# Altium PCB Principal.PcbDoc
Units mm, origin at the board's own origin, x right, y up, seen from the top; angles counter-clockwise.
Board outline 152.4 x 101.6 mm, 2 copper layers (Top Layer, Bottom Layer); 38 components, 56 nets, 194 pads, 50 vias.
Unrouted connection lines stored in the file: 1.
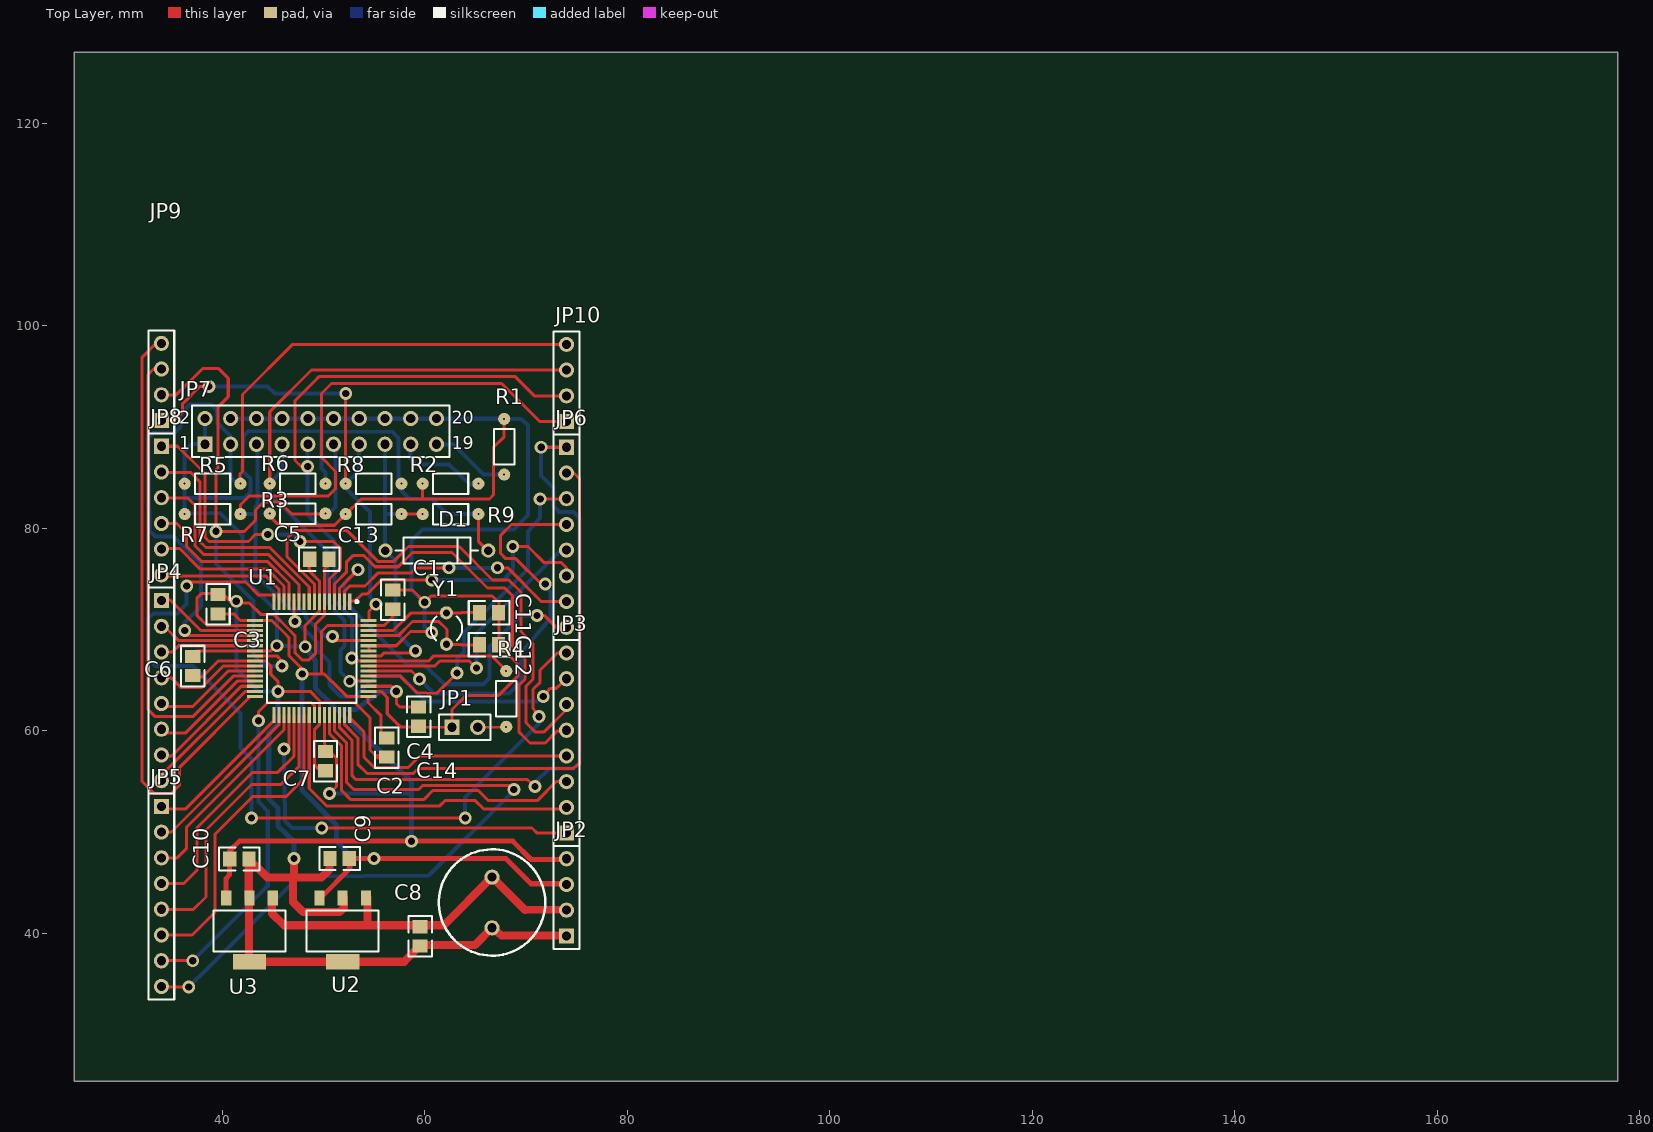
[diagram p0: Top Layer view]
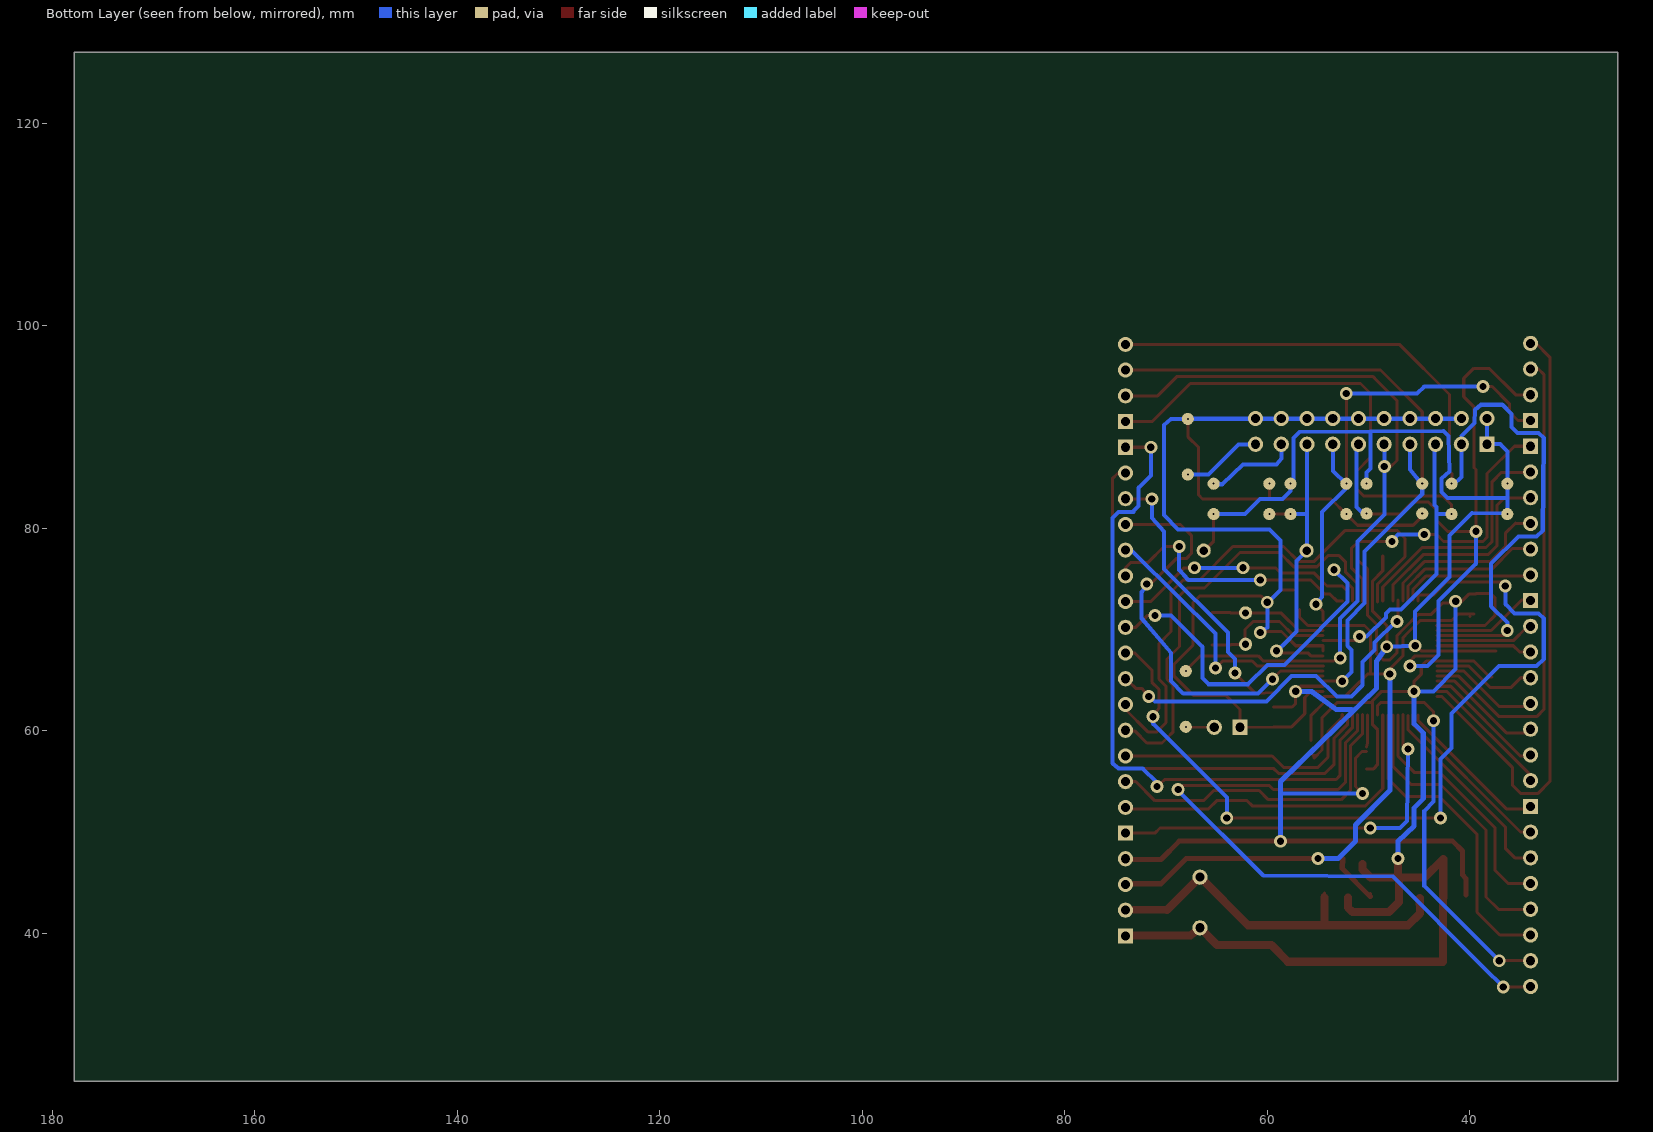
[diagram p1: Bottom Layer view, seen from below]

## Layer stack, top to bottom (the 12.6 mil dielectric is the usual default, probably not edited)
Top Layer: signal copper 0.0356
Dielectric: dielectric 0.32, FR-4, Dk 4.8
Bottom Layer: signal copper 0.0356

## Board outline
25.4,25.4 177.8,25.4 177.8,127 25.4,127

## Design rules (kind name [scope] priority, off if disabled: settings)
Clearance [All] p1: gap=0.2
ComponentClearance [All] p1: gap=0.254 collisioncheckmode=0
PolygonConnect [All] p1: connectstyle=Relief reliefconductorwidth=0.254 reliefentries=4 polygonreliefangle="90 Angle"
RoomDefinition Principal1 [InComponentClass('Principal1')] p1: confinementstyle=ConfineIn formatcopy=TRUE outline 0,0 50.8,0 50.8,25.4 0,25.4
RoutingLayers [All] p1: top layer=Horizontal bottom layer=Vertical
RoutingVias [All] p1: holewidth=0.711 width=1.27 viastyle="Through Hole" minholewidth=0.711 minwidth=1.27 maxholewidth=0.711 maxwidth=1.27
SolderMaskExpansion [All] p1: expansion=0.102
TestPointUsage [All] p1: valid=0 allowmultiple=FALSE
Testpoint [All] p1: side=15 testpointundercomponent=TRUE minsize=1.016 maxsize=2.54 preferedsize=1.524 minholesize=0 maxholesize=1.016 preferedholesize=0.813 testpointgrid=0.025 style=1023 order=1234567890
Width [All] p1: maxlimit=0.8 minlimit=0.2 preferedwidth=0.2 toplayer_prefwidth=0.3 bottomlayer_prefwidth=0.4 minimp=50.000000 maximp=50.000000 favimp=50.000000
16 further rules are at their usual default settings.

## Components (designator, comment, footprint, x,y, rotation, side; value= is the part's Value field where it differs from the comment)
C1 "Cap" R2012-0805 56.85,72.95 r270 top
C2 "Cap" R2012-0805 56.25,58.35 r90 top
C3 "Cap" R2012-0805 39.6,72.5 r270 top
C4 "Cap" R2012-0805 59.4,61.4 r90 top
C5 "Cap" R2012-0805 49.6,76.95 r180 top
C6 "Cap" R2012-0805 37.1,66.4 r90 top
C7 "Cap" R2012-0805 50.2,57 r90 top
C8 "Cap" R2012-0805 59.55,39.7 r90 top
C9 "Cap" R2012-0805 51.6,47.4 r0 top
C10 "Cap" R2012-0805 41.7,47.35 r180 top
C11 "Cap" R2012-0805 66.35,71.65 r0 top
C12 "Cap" R2012-0805 66.35,68.5 r0 top
C13 "Cap" "Res 5mm" 57.7,81.4 r180 top
C14 "Cap Pol1" RB5-10.5 66.65,43.05 r270 top
D1 "Diode" DIODE-0.4 61.2,77.8 r0 top
JP1 "JTAG" HDR1X2 62.7,60.35 r0 top
JP2 "Header 4" HDR1X4 74,39.75 r90 top
JP3 "Header 8" HDR1X8 74,49.9 r90 top
JP4 "Header 8" HDR1X8 34,72.86 r270 top
JP5 "Header 8" HDR1X8 34,52.54 r270 top
JP6 "Header 8" HDR1X8 74,88 r270 top
JP7 "JTAG P5" HDR2X10 38.3,88.3 r0 top
JP8 "Header 6" HDR1X6 34,88.1 r270 top
JP9 "Header 4" HDR1X4 34,90.64 r90 top
JP10 "Header 4" HDR1X4 74,90.54 r90 top
R1 "Res1" "Res 5mm" 67.85,85.3 r90 top
R2 "Res1" "Res 5mm" 65.3,84.4 r180 top
R3 "Res1" "Res 5mm" 50.2,81.45 r180 top
R4 "Res1" "Res 5mm" 68.05,65.9 r270 top
R5 "Res1" "Res 5mm" 36.3,84.4 r0 top
R6 "Res1" "Res 5mm" 50.2,84.4 r180 top
R7 "Res1" "Res 5mm" 36.3,81.4 r0 top
R8 "Res1" "Res 5mm" 57.7,84.4 r180 top
R9 "Res1" "Res 5mm" 59.8,81.4 r0 top
U1 "LPC2114/LPC2124" F-QFP10X10-G64/P.5N 48.85,67.15 r270 top
U2 "LD1117S18" SOT223 58,37.2 r180 top
U3 "LD1117S33" SOT223 48.8,37.2 r180 top
Y1 "XTAL 16Mhz" BCY-W2/D3.1 62.15,70.1 r180 top

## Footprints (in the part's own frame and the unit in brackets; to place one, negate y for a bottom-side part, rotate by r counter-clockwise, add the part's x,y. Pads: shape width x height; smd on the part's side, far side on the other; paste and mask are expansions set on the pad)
BCY-W2/D3.1 [mm]
  round 1.3 hole 0.7: 1(0,1.55) 2(0,-1.55)
  silkscreen extent -1.55,-1.19 1.55,1.17
DIODE-0.4 [mm]
  round 1.4 hole 0.85: 1(-5.08,0) 2(5.08,0)
  silkscreen extent -4.06,-1.27 4.06,1.27
F-QFP10X10-G64/P.5N [mm]
  rect 1.6x0.3 smd: 1(-5.6,3.75) 2(-5.6,3.25) 3(-5.6,2.75) 4(-5.6,2.25) 5(-5.6,1.75) 6(-5.6,1.25) 7(-5.6,0.75) 8(-5.6,0.25) 9(-5.6,-0.25) 10(-5.6,-0.75) 11(-5.6,-1.25) 12(-5.6,-1.75) 13(-5.6,-2.25) 14(-5.6,-2.75) 15(-5.6,-3.25) 16(-5.6,-3.75) 33(5.6,-3.75) 34(5.6,-3.25) 35(5.6,-2.75) 36(5.6,-2.25) 37(5.6,-1.75) 38(5.6,-1.25) 39(5.6,-0.75) 40(5.6,-0.25) 41(5.6,0.25) 42(5.6,0.75) 43(5.6,1.25) 44(5.6,1.75) 45(5.6,2.25) 46(5.6,2.75) 47(5.6,3.25) 48(5.6,3.75)
  rect 0.3x1.6 smd: 17(-3.75,-5.6) 18(-3.25,-5.6) 19(-2.75,-5.6) 20(-2.25,-5.6) 21(-1.75,-5.6) 22(-1.25,-5.6) 23(-0.75,-5.6) 24(-0.25,-5.6) 25(0.25,-5.6) 26(0.75,-5.6) 27(1.25,-5.6) 28(1.75,-5.6) 29(2.25,-5.6) 30(2.75,-5.6) 31(3.25,-5.6) 32(3.75,-5.6) 49(3.75,5.6) 50(3.25,5.6) 51(2.75,5.6) 52(2.25,5.6) 53(1.75,5.6) 54(1.25,5.6) 55(0.75,5.6) 56(0.25,5.6) 57(-0.25,5.6) 58(-0.75,5.6) 59(-1.25,5.6) 60(-1.75,5.6) 61(-2.25,5.6) 62(-2.75,5.6) 63(-3.25,5.6) 64(-3.75,5.6)
  silkscreen extent -5.72,-4.4 4.4,4.58
HDR1X2 [mm]
  rect 1.5x1.5 hole 0.9: 1(0,0)
  round 1.5 hole 0.9: 2(2.54,0)
  silkscreen extent -1.27,-1.27 3.81,1.27
HDR1X4 [mm]
  rect 1.5x1.5 hole 0.9: 1(0,0)
  round 1.5 hole 0.9: 2(2.54,0) 3(5.08,0) 4(7.62,0)
  silkscreen extent -1.27,-1.27 8.89,1.27
HDR1X6 [mm]
  rect 1.5x1.5 hole 0.9: 1(0,0)
  round 1.5 hole 0.9: 2(2.54,0) 3(5.08,0) 4(7.62,0) 5(10.16,0) 6(12.7,0)
  silkscreen extent -1.27,-1.27 13.97,1.27
HDR1X8 [mm]
  rect 1.5x1.5 hole 0.9: 1(0,0)
  round 1.5 hole 0.9: 2(2.54,0) 3(5.08,0) 4(7.62,0) 5(10.16,0) 6(12.7,0) 7(15.24,0) 8(17.78,0)
  silkscreen extent -1.27,-1.27 19.05,1.27
HDR2X10 [mm]
  rect 1.5x1.5 hole 0.9: 1(0,0)
  round 1.5 hole 0.9: 2(0,2.54) 3(2.54,0) 4(2.54,2.54) 5(5.08,0) 6(5.08,2.54) 7(7.62,0) 8(7.62,2.54) 9(10.16,0) 10(10.16,2.54) 11(12.7,0) 12(12.7,2.54) 13(15.24,0) 14(15.24,2.54) 15(17.78,0) 16(17.78,2.54) 17(20.32,0) 18(20.32,2.54) 19(22.86,0) 20(22.86,2.54)
  silkscreen extent -1.27,-1.27 24.13,3.81
R2012-0805 [mm]
  rect 1.3x1.5 smd: 1(-0.95,0) 2(0.95,0)
  silkscreen extent -2,-1.15 2,1.15
RB5-10.5 [mm]
  round 1.5 hole 0.9: 1(-2.5,0) 2(2.5,0)
  silkscreen extent -5.25,-5.25 5.25,5.25
"Res 5mm" [mm]
  round 1.2 hole 0.2: 1(0,0) 2(5.5,0)
  silkscreen extent 1,-1.02 4.5,1.02
SOT223 [mm]
  rect 1x1.5 smd: 1(3.8,-6.3) 3(8.4,-6.3) 4(6.1,-6.3)
  rect 3.3x1.5 smd: 4(6.096,0)
  silkscreen extent 2.54,-5.08 9.65,-1.02

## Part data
C1 C2 C3 C4 C5 C6 C7 C8 C9 C10 C11 C12 C13: "Capacitor"
C14: "Polarized Capacitor (Radial)"
D1: "Default Diode"
JP1 JP2: library part "Header 2", "Header, 2-Pin"
JP3 JP4 JP5 JP6: "Header, 8-Pin"
JP7: library part "Header 10X2", "Header, 10-Pin, Dual row"
JP8: "Header, 6-Pin"
JP9: library part "Header 8", "Header, 8-Pin"
JP10: "Header, 4-Pin"
R1 R2 R3 R4 R5 R6 R7 R8 R9: "Resistor"
U2 U3: library part LF27ACDT, "Very Low Drop Voltage Regulator with Inhibit"
Y1: library part XTAL, "Crystal Oscillator"

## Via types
v1: diameter 1.27, hole 0.711, Top Layer to Bottom Layer, 50 vias

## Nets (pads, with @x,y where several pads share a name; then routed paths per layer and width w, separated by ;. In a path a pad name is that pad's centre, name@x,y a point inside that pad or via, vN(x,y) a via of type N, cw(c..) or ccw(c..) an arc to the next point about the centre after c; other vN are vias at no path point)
GND: C1.1 C2.1 C3.1 C4.1 C5.1 C6.1 C7.1 C8.1 C9.1 C10.1 C11.2 C12.2 C13.2 C14.2 JP1.1 JP2.1 JP7.4 JP7.6 JP7.8 JP7.10 JP7.12 JP7.14 JP7.16 JP7.18 JP7.20 R1.2 R2.2 R3.2 U1.6 U1.18 U1.25 U1.42 U1.50 U1.58 U1.59 U2.4 U3.4 | length 300.2
  Top Layer w0.3: C6.1@37.8,65.3 38,65.3 39.6,66.9 U1.25 44.3,66.9 44.8,66.4 44.8,65.6 45.5,64.9 v1(45.5,63.9) 48.7,63.9 49.6,63 49.6,60.6 49.1,60.1 49.1,56.7 49.5,56.25 C7.1@50.2,56.25 ; U1.18@43.3,70.4 38.5,70.4 37.5,71.4 37.5,73.1 37.95,73.55 39.4,73.55 39.45,73.5 40.1,73.5 41,72.6 42.7,72.6 43.8,71.5 45.1,71.5 46.5,70.1 47.2,69.4 47.2,67.7 47.9,67 48.578,67.005 49.2,67.6 49.2,70.5 50.1,71.4 50.1,76 C5.1@50.9,76.7 ; R3.2@44.4,81.5 45.6,80.3 49.5,80.3 51.1,80.3 C13.2 53.7,82.9 66.4,82.9 66.8,83.3 66.8,88 67.85,89.05 R1.2 ; 49.6,62.8 53.1,62.8 54.6,61.3 54.6,58.1 55.4,57.3 ; U1.50@54.5,63.9 55.7,63.9 56.3,63.3 56.3,61.7 57.6,60.4 58.9,60.4 59.399,60.393 JP1.1 62.7,62.1 64.1,63.5 67.3,63.5 69.2,65.4 69.2,66.6 67.334,68.464 67.334,71.664 67.334,72.666 66.7,73.3 60.6,73.3 v1(60,72.7) 58.8,73.9 C1.1@57.35,73.9 ; U1.58@54.5,67.9 54.5,68.4 57.2,68.4 58.6,69.8 v1@60.1,69.8 ; 55.3,57.55 55.5,57.55 ; 59.8,82.9 R2.2@59.8,84.35 ; JP7.20@61.144,90.816 JP7.20@61.144,90.83
  Top Layer w0.8: 47,45.5 47,43.1 48,42.1 51.6,42.1 52.05,42.55 U2.4@52.05,43.55 ; 47.1,45.5 v1(47.1,47.4) ; C9.1@50.6,46.847 50.6,46.3 49.8,45.5 44.474,45.5 42.626,47.348 42.626,43.524 42.654,43.496 42.654,37.2 52.054,37.2 58,37.2 58,37.25 59.6,38.85 64.95,38.85 C14.2 ; C14.2@66.55,40.55 67.6,39.8 JP2.1@73.5,39.8
  Bottom Layer w0.4: JP7.4@40.824,90.816 67.834,90.816 R1.2 69.5,90.8 70.2,90.2 70.2,81.3 68.8,79.9 59.8,79.9 58.7,78.8 58.7,73.9 59.9,72.7 v1(60,72.7) 60,70.2 v1(60.7,69.7) ; v1(41.4,72.8) 41.4,66.1 43.6,63.9 v1(45.5,63.9)
  Bottom Layer w0.5: v1(45.5,63.9) 45.5,60.7 44.6,59.8 44.6,53.3 45.5,52.4 45.5,50.6 47.1,49.1 v1(47.1,47.4)
NetC1_2: C1.2 C2.2 C3.2 C9.2 JP2.3 U1.17 U1.49 U1.63 U2.3 | length 86.7
  Top Layer w0.3: C3.2 41.15,71.55 41.8,70.9 44.9,70.9 46.1,69.7 46.6,69.2 46.6,67.4 47.9,66.1 v1(47.9,65.6) 49.4,65.6 50.1,65.6 51.5,64.2 52.3,63.4 54.4,63.4 54.4,62.8 55.7,61.5 C2.2@55.7,59.05 ; 49.8,65.6 49.8,69.8 50.4,70.4 56,70.4 56.8,71.2 C1.2@56.8,72 ; U2.3@49.834,43.628 U2.3@49.834,43.917
  Top Layer w0.5: U2.3@49.834,43.628 52.6,46.4 C9.2 68,47.4 70.5,44.9 JP2.3@73.7,44.9
  Bottom Layer w0.5: v1(47.9,65.6) 47.9,54.1 51.3,50.7 51.3,49.1 53,47.4 v1(55,47.4)
NetC4_2: C4.2 C5.2 C6.2 C7.2 C10.2 D1.2 JP2.4 JP7.1 JP7.2 R5.1 R6.1 R7.1 R8.1 R9.2 U1.7 U1.23 U1.43 U1.51 U3.3 | length 193.7
  Top Layer w0.3: C6.2@37.4,67.9 44.8,67.9 v1(45.4,68.4) ; v1@48.158,68.25 v1(48.2,68.3) 48.2,70.4 49.6,71.8 49.6,74.8 48.6,75.8 C5.2@48.6,77.25 ; U1.43 50.1,58.8 C7.2@50.2,58.4 ; C7.2 50.65,57.95 51.3,57.3 51.3,54.5 v1(50.6,53.8) ; U1.51@54.5,64.4 56.7,64.4 v1(57.2,63.9) 57.2,62.7 57.55,62.35 C4.2 ; R9.2 65.3,78.73 D1.2@66.23,77.8
  Top Layer w0.5: U3.3@40.4,43.8 40.4,45.4 40.726,45.775 40.726,48.126 41.7,49.1 v1(58.7,49.1) 68.7,49.1 70.5,47.3 JP2.4@74.3,47.32
  Bottom Layer w0.4: 36.3,83 42.2,83 42.8,83.6 42.8,84.9 42,85.6 42.1,89.1 42.6,89.6 49.8,89.549 56.8,89.5 57.4,88.9 R8.1@57.4,84.5 ; JP7.1@38.284,88.276 JP7.2@38.284,90.816 ; JP7.1 37,88.3 36.3,87.6 36.3,84.2 36.3,81.45 39.8,81.5 42,79.3 42,75.2 45.4,71.8 v1(45.4,68.4) v1@48.108,68.3 ; 49.8,89.5 49.8,85.9 50.2,85.5 R6.1@50.2,84.35 ; v1(50.6,53.8) 58.7,53.8 ; R8.1 57.7,83.7 58.5,82.9 60.7,82.9 62.2,81.4 R9.2
  Bottom Layer w0.5: v1(48.2,68.3) 49.2,66.9 49.2,64.2 58.7,55 v1(58.7,49.1) ; 51.7,62.1 53.2,62.1 55.659,63.904 v1@57.1,63.9
NetC8_2: C8.2 C14.1 JP2.2 U2.1 U3.1 | length 37.6
  Top Layer w0.3: U2.1@54.334,44.009 54.334,43.79 U2.1@54.553,43.79
  Top Layer w0.8: U3.1@44.95,43.5 44.934,41.966 46.1,40.8 61.9,40.8 C14.1 69.9,42.3 JP2.2@74,42.34 ; 54.3,40.8 54.35,40.85 U2.1@54.35,43.55
NetC11_1: C11.1 U1.62 Y1.2 | length 11.7
  Top Layer w0.3: U1.62@54.5,69.9 56.9,69.9 58.614,71.614 63.576,71.614 63.626,71.664 C11.1@65.434,71.664
NetC12_1: C12.1 U1.61 Y1.1 | length 13.4
  Top Layer w0.3: U1.61@54.5,69.4 57.4,69.4 58.8,70.8 61.4,70.8 62.2,70 62.184,68.514 63.576,68.514 63.626,68.464 C12.1@65.434,68.464
NetC13_1: C13.1 D1.1 JP7.15 R9.1 U1.57 | length 30.2
  Top Layer w0.3: U1.57@54.5,67.4 55.7,67.4 56,67.7 58.7,67.7 v1(59.1,67.9) ; C13.1 R9.1
  Bottom Layer w0.4: 56.064,81.4 C13.1 ; JP7.15@56.064,88.276 56.064,77.806 57.1,76.77 57.1,69.8 58.4,68.5 v1(59.1,67.9)
NetJP1_2: JP1.2 R4.2 | length 2.9
  Top Layer w0.3: JP1.2 R4.2 R4.2@68.1,60.45
NetJP3_1: JP3.1 U1.36 | length 39.1
  Top Layer w0.3: v1(46.1,58.2) 46.6,58.5 U1.36 U1.36@46.6,61.625 ; v1(49.835,50.394) 70.6,50.4 71.1,49.9 JP3.1
  Bottom Layer w0.4: v1(46.1,58.2) 46.2,51.1 46.906,50.394 v1(49.835,50.394)
NetJP3_2: JP3.2 U1.40 | length 33.5
  Top Layer w0.3: U1.40 48.6,60.409 48.6,54.3 50.3,52.6 61.5,52.6 62,53.1 65,53.1 65.8,52.3 JP3.2@73.6,52.3
NetJP3_3: JP3.3 U1.44 | length 32.1
  Top Layer w0.3: U1.44@50.6,61.6 50.6,59.7 51.8,58.5 51.8,54.1 52.7,53.2 59.9,53.2 60.8,54.1 65.3,54.1 66.3,53.1 71.1,53.1 73,55 JP3.3
NetJP3_4: JP3.4 U1.48 | length 25.7
  Top Layer w0.3: U1.48@52.6,61.6 52.6,61.3 54,59.9 54,57.4 55,56.4 58.4,56.4 59.52,57.52 JP3.4
NetJP3_5: JP3.5 U1.4 | length 43.3
  Top Layer w0.3: U1.4@51.1,72.8 51.1,74.5 52.3,75.7 52.3,76.7 52.9,77.3 54,77.3 55.1,76.2 57.4,76.2 58.8,77.6 62.7,77.6 66.2,74.1 67.9,74.1 68.676,73.324 68.676,68.324 69.9,67.1 69.9,65.1 69.3,64.5 69.3,59.9 69.9,59.3 70.4,58.8 71.9,58.8 73.1,60 JP3.5@73.6,60
NetJP3_6: JP3.6 U1.8 | length 54.1
  Top Layer w0.3: U1.8@49.1,72.7 49.1,74.5 46.4,77.2 46.4,79 47.2,79.8 52.3,79.8 55.4,76.7 56.9,76.7 58.4,78.2 63.4,78.2 66.7,74.9 68.3,74.9 69.5,73.7 69.5,69.8 70.7,68.6 70.7,65.1 70,64.4 70,60.8 70.9,59.9 71.8,59.9 74,62.1 JP3.6
NetJP3_7: JP3.7 U1.12 | length 36
  Top Layer w0.3: U1.12@47.1,72.9 47.1,71.1 v1(47.2,70.8) ; v1(71.7,63.4) 72.4,64.2 73,64.2 JP3.7@73.6,64.8
  Bottom Layer w0.4: v1(47.2,70.8) 47.3,70.8 49.4,68.7 49.4,68 50.6,66.8 50.6,64.5 51.7,63.4 53.1,63.4 55.2,65.4 57.6,65.4 60.1,62.9 71.1,62.9 v1(71.7,63.4)
NetJP3_8: JP3.8 U1.16 | length 84.9
  Top Layer w0.3: v1@36.5,74.7 42.3,74.7 43.6,73.4 45.1,73.4 U1.16@45.1,72.8 ; v1(42.9,51.4) v1(64,51.4) v1@64.135,51.714 ; v1(71.3,61.4) 70.7,62.2 70.7,64.1 71.4,64.8 71.4,66 73.08,67.68 JP3.8
  Bottom Layer w0.4: v1(36.5,74.3) 36.5,72.5 35.6,71.6 33.2,71.6 32.7,71.1 32.7,67.1 33.4,66.4 37.1,66.4 41.8,61.7 41.8,58.3 42.9,57.2 v1(42.9,51.4) ; v1(64,51.4) 64,53.4 71.3,60.7 v1(71.3,61.4)
NetJP4_1: JP4.1 U1.19 | length 10.1
  Top Layer w0.3: JP4.1@34.4,72.9 34.9,72.9 37.9,69.9 U1.19
NetJP4_2: JP4.2 U1.21 | length 9.8
  Top Layer w0.3: JP4.2 34.4,70.2 35.7,68.9 U1.21
NetJP4_3: JP4.3 U1.22 | length 9.2
  Top Layer w0.3: JP4.3@34.3,67.8 35.1,67.8 35.7,68.4 U1.22
NetJP4_4: JP4.4 U1.26 | length 10.5
  Top Layer w0.3: JP4.4 34.96,65.24 35.9,64.3 38,64.3 40.1,66.4 U1.26
NetJP4_5: JP4.5 U1.27 | length 10.5
  Top Layer w0.3: JP4.5@34.2,62.4 37.1,62.4 40.6,65.9 U1.27
NetJP4_6: JP4.6 U1.29 | length 11.3
  Top Layer w0.3: JP4.6@34.1,59.8 36.4,59.8 41.5,64.9 U1.29
NetJP4_7: JP4.7 U1.30 | length 11.9
  Top Layer w0.3: JP4.7@34.2,57.5 35,57.5 41.9,64.4 U1.30
NetJP4_8: JP4.8 U1.31 | length 12.7
  Top Layer w0.3: JP4.8@34,55.6 42.3,63.9 U1.31
NetJP5_1: JP5.1 U1.33 | length 15
  Top Layer w0.3: JP5.1@34.3,52.3 36.4,52.3 45.1,61 U1.33
NetJP5_2: JP5.2 U1.34 | length 17
  Top Layer w0.3: JP5.2 35,50 45.6,60.6 U1.34 U1.34@45.6,61.625
NetJP5_3: JP5.3 U1.35 | length 20
  Top Layer w0.3: JP5.3 35.56,47.46 36.5,48.4 36.5,50.5 46.1,60.1 U1.35@46.1,61.525
NetJP5_4: JP5.4 U1.37 | length 24.8
  Top Layer w0.3: JP5.4 36.22,44.92 37.5,46.2 37.5,50.4 43,55.9 45.5,55.9 47.1,57.5 U1.37
NetJP5_5: JP5.5 U1.38 | length 28.4
  Top Layer w0.3: JP5.5 37.18,42.38 38.4,43.6 38.4,50.2 42.9,54.7 45.8,54.7 47.6,56.5 47.6,60.709 U1.38
NetJP5_6: JP5.6 U1.39 | length 31.3
  Top Layer w0.3: JP5.6 37.04,39.84 39.3,42.1 39.3,49.8 43,53.5 46.3,53.5 48.1,55.3 U1.39
NetJP5_7: JP5.7 U1.41 | length 37.8
  Top Layer w0.3: JP5.7@34.3,37.3 v1(37.1,37.3) ; v1(43.6,61) 43.6,61.9 44.5,62.8 48.8,62.8 49.1,62.5 U1.41
  Bottom Layer w0.4: v1(37.1,37.3) 44.5,44.7 44.5,52.1 43.6,53 v1(43.6,61)
NetJP5_8: JP5.8 U1.45 | length 66.9
  Top Layer w0.3: JP5.8@34.3,34.7 v1(36.7,34.7) ; U1.45@51.1,61.6 51.1,60 52.3,58.8 52.3,54.9 53,54.2 59.4,54.2 59.8,54.6 68.3,54.6 v1(68.8,54.2)
  Bottom Layer w0.4: v1(36.7,34.7) 38.6,36.6 47.6,45.6 60.4,45.7 68.7,54 v1(68.8,54.2)
NetJP6_1: JP6.1 U1.46 | length 66.7
  Top Layer w0.3: U1.46@51.6,61.6 51.6,60.3 52.8,59.1 52.8,55.6 53.2,55.2 70.1,55.2 v1(70.9,54.5) ; v1(71.5,88) JP6.1
  Bottom Layer w0.4: v1(70.9,54.5) 70.9,54.9 72.3,56.3 74.7,56.3 75.3,56.8 75.3,81 74.7,81.6 73.2,81.6 73.2,81.7 72.7,82.2 72.7,84 71.5,85.2 v1(71.5,88)
NetJP6_2: JP6.2 U1.47 | length 57.3
  Top Layer w0.3: U1.47@52.1,61.5 52.1,60.6 53.4,59.3 53.4,56.7 54.3,55.8 58.9,55.8 59.4,56.3 74.7,56.3 75.3,56.8 75.3,84.9 74.8,85.4 JP6.2@74.3,85.4
NetJP6_3: JP6.3 U1.53 | length 33.3
  Top Layer w0.3: U1.53@54.5,65.4 57.6,65.4 59.2,63.8 61.2,63.7 v1(63.2,65.7) ; v1(71.4,82.9) JP6.3@73.98,82.9
  Bottom Layer w0.4: v1(63.2,65.7) 63.2,67.1 63.9,67.8 63.9,69.7 70.2,76 70.2,79.7 71.4,81 v1(71.4,82.9)
NetJP6_4: JP6.4 U1.54 | length 41.6
  Top Layer w0.3: U1.54@54.5,65.9 58.7,65.9 v1(59.5,65.1) ; v1(71.9,74.5) 71.5,74.5 69,77 68,77 67.5,77.5 67.5,79.3 68.58,80.38 JP6.4
  Bottom Layer w0.4: v1(59.5,65.1) 60.9,63.7 68.3,63.7 69.5,64.9 69.5,67.7 72.4,71.1 72.4,73.7 v1(71.9,74.5)
NetJP6_5: JP6.5 U1.55 | length 26.8
  Top Layer w0.3: U1.55 61,66.4 61.5,66.9 64.4,66.9 v1(65.1,66.2)
  Bottom Layer w0.4: v1(65.1,66.2) 65.1,69.6 73,77.4 73.4,77.8 JP6.5
NetJP6_6: JP6.6 U1.1 | length 26.7
  Top Layer w0.3: U1.1@52.6,72.8 53.1,72.8 53.8,73.5 54.3,73.5 55.7,74.9 v1(60.7,74.9) ; v1(68.7,78.2) 70.2,78.2 71.8,76.6 73.5,76.6 74,76.1 JP6.6
  Bottom Layer w0.4: v1(60.7,74.9) 67.8,74.9 68.7,75.9 v1(68.7,78.2)
NetJP6_7: JP6.7 U1.2 | length 25.4
  Top Layer w0.3: U1.2@52.1,72.6 52.1,73.8 52.6,74.3 54.1,74.3 55.4,75.6 58.7,75.6 59.2,76.1 v1(62.4,76.1) ; v1(67.2,76.1) 68.2,76.1 71.54,72.76 JP6.7
  Bottom Layer w0.4: v1(62.4,76.1) v1(67.2,76.1)
NetJP6_8: JP6.8 U1.3 | length 38.3
  Top Layer w0.3: U1.3@51.6,72.8 51.6,74.1 52.9,75.4 v1(53.4,75.9) ; v1(71.1,71.4) 71.8,71.4 72.98,70.22 JP6.8 JP6.8@73.72,70.5
  Bottom Layer w0.4: v1(53.4,75.9) 52.1,74.6 52.1,72.75 57.4,67.4 58.3,66.5 60,66.5 61.9,64.6 65.8,64.6 66.4,65.2 66.4,68.3 69.5,71.4 v1(71.1,71.4)
NetJP7_3: JP7.3 JP10.4 R5.2 U1.20 | length 91.2
  Top Layer w0.3: v1(36.3,69.9) 36.4,69.4 U1.20 ; R5.2@41.75,84.2 41.75,85.35 42,85.6 42,93.2 46.96,98.16 JP10.4
  Bottom Layer w0.4: v1(36.3,69.9) 36.3,70.7 37.9,72.3 37.9,76.5 35.2,79.2 33.4,79.2 32.8,79.8 32.7,88.5 32.7,88.9 33.2,89.4 35.3,89.4 35.9,90 35.9,91.3 36.8,92.2 38.9,92.2 39.5,91.7 39.548,90.379 40.824,89.103 40.824,85.076 41.677,84.269 41.75,84.2 R5.2@41.45,84.35
NetJP7_5: JP7.5 JP10.1 R7.2 U1.60 | length 75.7
  Top Layer w0.3: R7.2 41.8,82.3 42.7,83.2 50.5,83.2 51.2,83.9 51.2,85.6 49.8,87 49.8,93.3 50.8,94.3 67.6,94.3 71.36,90.54 JP10.1 ; v1(50.9,69.3) 51.3,68.9 U1.60@54.5,68.9
  Bottom Layer w0.4: R7.2 43.283,81.4 ; JP7.5@43.364,88.276 JP7.5@43.383,88.276 ; JP7.5 43.5,88.18 43.5,82.3 43.3,82.1 43.3,75.5 46.8,72 47.9,72 48.3,71.6 48.3,71.2 50.2,69.3 v1(50.9,69.3)
NetJP7_7: JP7.7 JP10.3 R6.2 U1.52 | length 68.4
  Top Layer w0.3: R6.2@44.65,84.35 44.7,84.6 44.7,91.5 48.82,95.62 JP10.3 ; v1@52.9,65 v1(52.6,64.9) ; v1@52.9,65.3 v1(52.6,64.9) ; U1.52@54.5,64.9 v1(52.6,64.9)
  Bottom Layer w0.4: JP7.7@45.9,88.38 45.904,88.276 45.904,85.804 44.7,84.3 44.7,83.4 45.4,82.7 46.5,81.6 50.4,77.7 50.4,72.6 52.1,70.9 52.1,68.4 51.7,68 51.7,65.8 51.8,65.7 v1(52.6,64.9)
NetJP7_9: JP7.9 JP10.2 R4.1 U1.56 | length 75.6
  Top Layer w0.3: v1@48.9,86.1 47.8,86.1 47.2,86.7 47.2,92.6 49.2,94.6 49.6,95 68.9,95 70.82,93.08 JP10.2 ; v1(52.8,67.2) 53.5,66.9 60.4,66.9 60.9,67.4 66.6,67.4 68.1,65.9 R4.1 R4.1@68.1,65.95
  Bottom Layer w0.4: JP7.9@48.444,88.276 48.444,81.356 51.1,78.7 51.1,72.8 52.8,71.1 v1(52.8,67.2)
  other v1: 48.444,86.1
NetJP7_11: JP7.11 JP9.2 R3.1 U1.24 | length 63.9
  Top Layer w0.3: JP9.2 35.48,93.18 38.1,95.8 39.6,95.8 40.6,94.8 40.6,93 39.6,92 39.6,86 39.4,85.8 v1(39.4,79.7) 42.2,79.7 43.3,80.8 43.3,81.8 44.1,82.6 45.7,82.6 46.9,81.4 R3.1@49.9,81.4 ; U1.24@43.3,67.4 45.4,67.4 v1@45.9,66.9 ; R3.1 R3.1@50.4,81.4
  Bottom Layer w0.4: v1(39.4,79.7) 39.4,76.5 43.1,72.8 43.1,67.5 44.2,66.4 v1(45.9,66.4) ; R3.1@49.9,81.5 50.6,81.5 51.2,82.1 JP7.11@51.2,88
NetJP7_13: JP7.13 JP9.1 R8.2 U1.64 | length 48.8
  Top Layer w0.3: JP9.1 35.24,90.64 36.1,91.5 36.1,92.3 37.8,94 v1(38.7,94) ; R8.2@52.2,84.35 v1(52.2,93.3) ; U1.64@54.5,70.9 54.5,71.8 v1(55.2,72.5)
  Bottom Layer w0.4: v1(38.7,94) 44.5,94 45.2,93.3 v1(52.2,93.3) ; JP7.13@53.416,88.276 53.524,88.276 53.524,85.674 52.2,84.35 52.2,84 54.6,81.6 54.6,73.2 v1(55.2,72.5)
NetJP7_17: JP7.17 R2.1 | length 9.1
  Bottom Layer w0.4: JP7.17@58.604,88.276 58.604,86.896 59.1,86.3 62.4,86.3 64.45,84.35 R2.1@65.3,84.35
NetJP7_19: JP7.19 R1.1 | length 7.9
  Bottom Layer w0.4: JP7.19@61.144,88.276 62.824,88.276 63.961,87.139 65.8,85.3 R1.1
NetJP8_1: JP8.1 U1.5 | length 31.9
  Top Layer w0.3: JP8.1 35.6,88.1 38.3,85.4 38.3,79.1 38.7,78.7 42.6,78.7 43.3,79.4 v1(44.5,79.4) ; v1(47.7,78.7) 51,78.7 51.7,78 51.7,76.1 50.6,75 U1.5
  Bottom Layer w0.4: v1(44.5,79.4) 47.1,79.4 v1(47.7,78.7)
NetJP8_2: JP8.2 U1.9 | length 24.1
  Top Layer w0.3: JP8.2@34.06,85.5 36.9,85.5 37.8,84.6 37.8,78.7 38.4,78.1 44.7,78.1 48.6,74.2 U1.9@48.6,72.8
NetJP8_3: JP8.3 U1.11 | length 20.8
  Top Layer w0.3: JP8.3@34.3,83 36.6,83 37.3,82.3 37.3,78.3 38.2,77.4 44.6,77.4 47.6,74.4 U1.11@47.6,72.8
NetJP8_4: JP8.4 U1.13 | length 17.6
  Top Layer w0.3: JP8.4 35.48,80.48 ; 35.5,80.5 36.5,79.5 36.5,78.2 38,76.7 44.5,76.7 46.6,74.6 U1.13@46.6,72.8
NetJP8_5: JP8.5 U1.14 | length 14.9
  Top Layer w0.3: JP8.5@34.3,78 35.8,78 37.8,76 44.4,76 46.1,74.3 U1.14@46.1,72.7
NetJP8_6: JP8.6 U1.15 | length 13.3
  Top Layer w0.3: JP8.6 34.3,75.3 44.3,75.3 45.6,74 U1.15@45.6,72.9
NetJP9_3: JP9.3 U1.28 | length 47.1
  Top Layer w0.3: JP9.3 33.22,95.72 32.7,95.2 32.7,62.1 33.4,61.4 37.1,61.4 41.1,65.4 U1.28
NetJP9_4: JP9.4 U1.32 | length 60.5
  Top Layer w0.3: JP9.4@33.5,98.3 32.1,96.9 32.1,55 33.3,53.8 34.95,53.8 35.8,54.65 35.8,56.4 42.8,63.4 U1.32
pads on no net: U1.10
